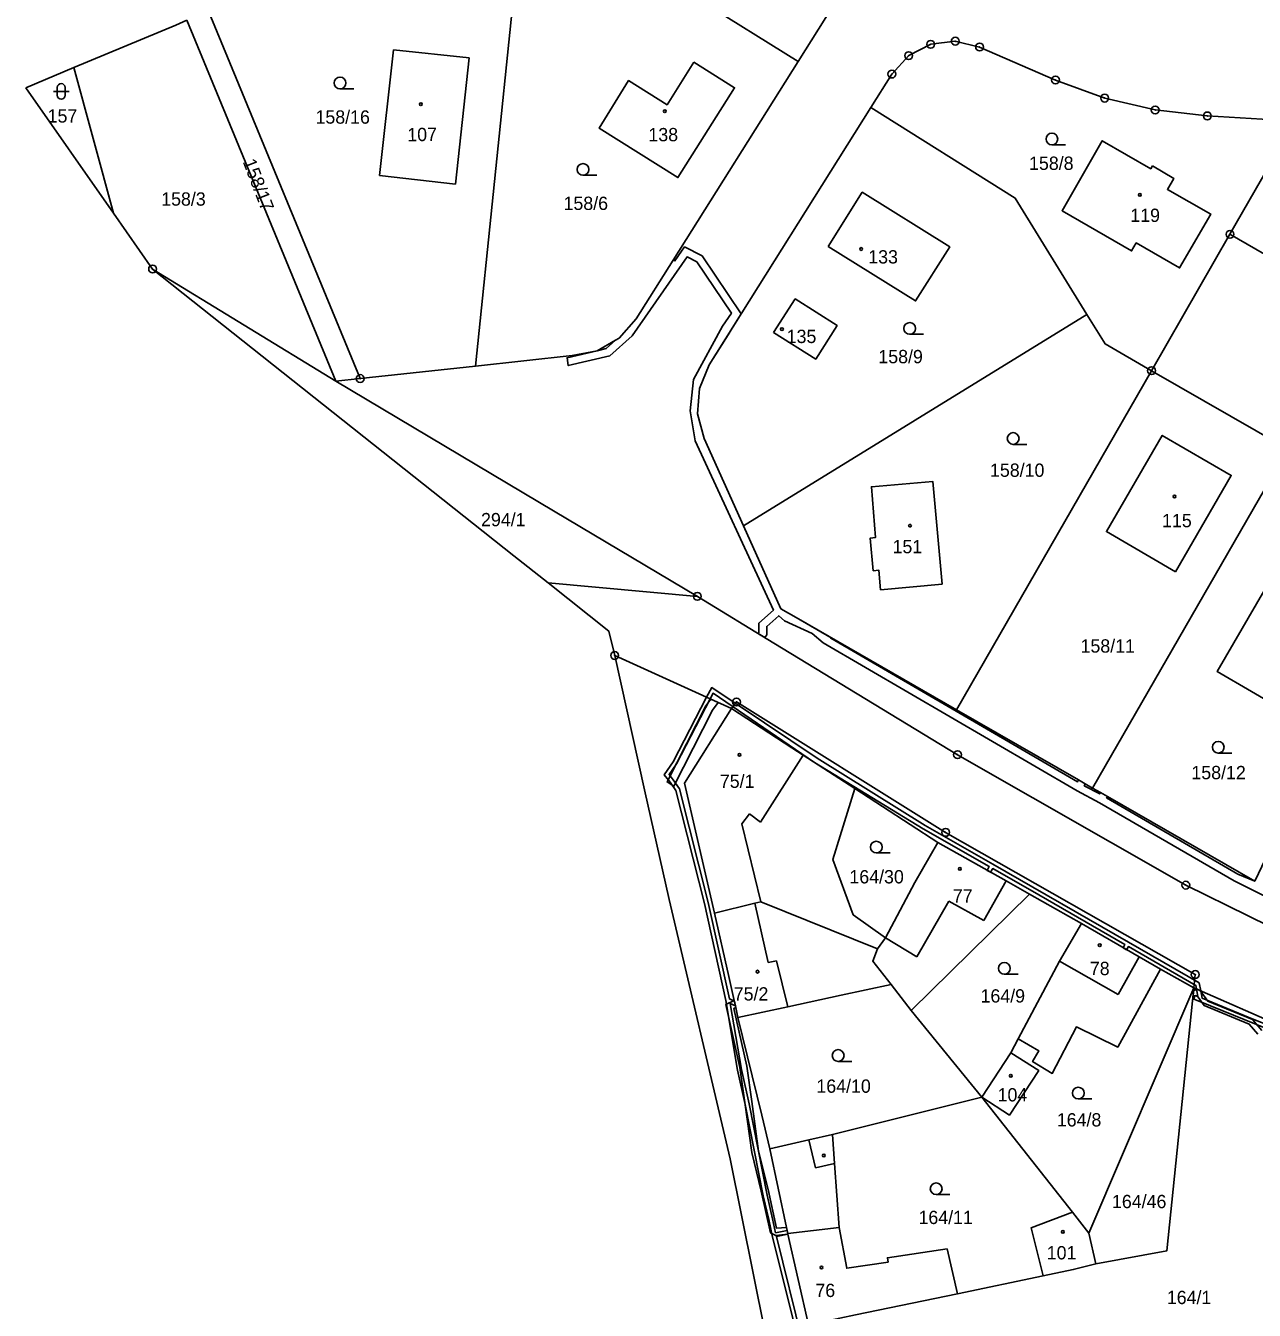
# Model space of a CAD drawing. Extents: x -779723 to -777378, y -1011169 to -1009297.
# Drawn here: x -779529.1 to -779372, y -1010177.1 to -1010012.9 of the extents above; entities that cross this region are included whole.
import ezdxf

# ---------------------------------------------------------------- set-up
doc = ezdxf.new("R2010")
doc.units = 0
for name, color, linetype in [('Hranice parcel', 7, 'Continuous'), ('Parcelní čísla', 7, 'Continuous'), ('Vnitřní kresba', 7, 'Continuous'), ('Věcná břemena k části', 7, 'Continuous'), ('Značky bodu BP', 7, 'Continuous'), ('Značky budov', 7, 'Continuous'), ('Značky kultur', 7, 'Continuous')]:
    doc.layers.add(name, color=color, linetype=linetype)

msp = doc.modelspace()

# ---------------------------------------------------------------- linework, layer by layer
at = {"layer": 'Hranice parcel'}
for p, q in [((-779405.63, -1009978.11), (-779430.36, -1010017.45)), ((-779466.49, -1010007.04), (-779471.6, -1010056.37)), ((-779505.72, -1010011.01), (-779486.32, -1010057.97)), ((-779489.42, -1010058.31), (-779508.48, -1010012.18)), ((-779522.9, -1010018.23), (-779529.07, -1010020.81)), ((-779517.85, -1010036.84), (-779522.9, -1010018.23)), ((-779529.07, -1010020.81), (-779517.85, -1010036.84)), ((-779517.85, -1010036.84), (-779512.85, -1010043.97)), ((-779385.17, -1010056.96), (-779375.15, -1010039.53)), ((-779512.85, -1010043.97), (-779489.42, -1010058.31)), ((-779512.85, -1010043.97), (-779466.67, -1010080.62)), ((-779437.34, -1010076.8), (-779393.43, -1010049.78)), ((-779459.24, -1010055.03), (-779471.6, -1010056.37)), ((-779471.6, -1010056.37), (-779486.32, -1010057.97)), ((-779410.1, -1010100.31), (-779385.17, -1010056.96)), ((-779367.78, -1010066.96), (-779385.17, -1010056.96)), ((-779486.32, -1010057.97), (-779489.42, -1010058.31)), ((-779392.71, -1010110.31), (-779367.78, -1010066.96)), ((-779466.67, -1010080.62), (-779462.29, -1010084.1)), ((-779462.29, -1010084.1), (-779443.22, -1010085.81)), ((-779412.49, -1010117.26), (-779423.11, -1010110.38)), ((-779415.89, -1010138.74), (-779400.78, -1010123.88)), ((-779394.14, -1010127.63), (-779400.78, -1010123.88)), ((-779420.18, -1010130.88), (-779419.17, -1010129.45)), ((-779379.75, -1010135.84), (-779384.01, -1010133.48)), ((-779418.47, -1010135.43), (-779415.89, -1010138.74)), ((-779393.19, -1010167.19), (-779379.75, -1010135.84)), ((-779368.25, -1010140.93), (-779379.75, -1010135.84)), ((-779415.89, -1010138.74), (-779406.87, -1010149.81)), ((-779402.22, -1010142.37), (-779403.16, -1010144.15)), ((-779406.87, -1010149.81), (-779403.16, -1010144.15)), ((-779425.97, -1010154.58), (-779406.87, -1010149.81)), ((-779406.87, -1010149.81), (-779395.28, -1010164.54)), ((-779395.28, -1010164.54), (-779393.19, -1010167.19)), ((-779392.31, -1010171.12), (-779393.19, -1010167.19)), ((-779409.96, -1010174.94), (-779411.28, -1010169.22)), ((-779399.03, -1010172.67), (-779409.96, -1010174.94))]:
    msp.add_line(p, q, dxfattribs=at)
for points in [[(-779430.36, -1010017.45), (-779443.07, -1010009.46), (-779466.49, -1010007.04)], [(-779508.48, -1010012.18), (-779509.9, -1010012.78), (-779522.9, -1010018.23)], [(-779482.07, -1010015.94), (-779472.39, -1010016.99), (-779474.14, -1010033.11), (-779483.83, -1010032.01), (-779482.07, -1010015.94)], [(-779421.04, -1010023.31), (-779418.36, -1010019.05), (-779416.21, -1010016.69), (-779413.4, -1010015.24), (-779410.26, -1010014.85), (-779407.15, -1010015.59), (-779397.45, -1010019.81), (-779391.16, -1010022.12), (-779384.71, -1010023.64), (-779378.05, -1010024.4), (-779366.83, -1010025.07)], [(-779430.36, -1010017.45), (-779446.32, -1010042.84), (-779451.04, -1010050.34), (-779453.2, -1010052.79), (-779453.68, -1010053.07), (-779456.04, -1010054.41), (-779459.24, -1010055.03)], [(-779443.68, -1010017.51), (-779438.46, -1010020.79), (-779445.71, -1010032.28), (-779455.79, -1010025.95), (-779452.01, -1010019.89), (-779447.1, -1010022.98), (-779443.68, -1010017.51)], [(-779437.34, -1010076.8), (-779442.37, -1010065.63), (-779443.2, -1010062.48), (-779442.97, -1010059.22), (-779441.71, -1010056.21), (-779421.04, -1010023.31)], [(-779421.04, -1010023.31), (-779402.59, -1010034.91), (-779393.43, -1010049.78)], [(-779375.15, -1010039.53), (-779371.1, -1010032.49), (-779369.72, -1010030.1), (-779366.83, -1010025.07)], [(-779385.04, -1010030.79), (-779382.33, -1010032.39), (-779383.14, -1010033.8), (-779377.61, -1010036.95), (-779381.6, -1010043.83), (-779387.12, -1010040.63), (-779387.72, -1010041.66), (-779396.61, -1010036.51), (-779391.47, -1010027.58), (-779385.28, -1010031.16), (-779385.04, -1010030.79)], [(-779426.49, -1010041.07), (-779422.15, -1010034.15), (-779410.97, -1010041.14), (-779415.34, -1010048.05), (-779426.49, -1010041.07)], [(-779341.93, -1010058.63), (-779356.91, -1010050.02), (-779361.56, -1010047.34), (-779375.15, -1010039.53)], [(-779433.48, -1010052.09), (-779430.71, -1010047.79), (-779425.37, -1010051.19), (-779428.1, -1010055.49), (-779433.48, -1010052.09)], [(-779393.43, -1010049.78), (-779391.11, -1010053.54), (-779385.17, -1010056.96)], [(-779489.42, -1010058.31), (-779461.6, -1010074.87), (-779443.22, -1010085.81)], [(-779382.13, -1010082.68), (-779390.94, -1010077.53), (-779383.8, -1010065.23), (-779374.99, -1010070.35), (-779382.13, -1010082.68)], [(-779411.92, -1010084.25), (-779419.8, -1010084.97), (-779420.01, -1010082.47), (-779420.75, -1010082.53), (-779421.12, -1010078.36), (-779420.44, -1010078.28), (-779420.98, -1010071.8), (-779413.13, -1010071.11), (-779411.92, -1010084.25)], [(-779410.1, -1010100.31), (-779430.6, -1010088.52), (-779432.57, -1010087.39), (-779437.34, -1010076.8)], [(-779350.39, -1010076.96), (-779371.98, -1010122.22), (-779390.82, -1010111.39), (-779391.69, -1010110.89), (-779392.71, -1010110.31)], [(-779368.02, -1010100.51), (-779376.78, -1010095.43), (-779369.65, -1010083.1), (-779360.78, -1010088.23), (-779368.02, -1010100.51)], [(-779462.29, -1010084.1), (-779454.55, -1010090.24), (-779453.79, -1010093.36)], [(-779443.22, -1010085.81), (-779433.43, -1010091.77), (-779409.97, -1010106.05), (-779380.8, -1010122.72), (-779356.88, -1010134.5), (-779331.75, -1010145.42), (-779302.03, -1010157.12), (-779292.12, -1010161.67)], [(-779438.86, -1010100.16), (-779441.59, -1010098.92), (-779442.04, -1010098.71), (-779453.79, -1010093.36)], [(-779453.79, -1010093.36), (-779449.96, -1010110.52), (-779446.83, -1010124.56)], [(-779438.86, -1010100.16), (-779444.86, -1010109.68), (-779441.05, -1010126.3)], [(-779423.11, -1010110.38), (-779429.69, -1010106.11), (-779431.13, -1010105.19), (-779438.86, -1010100.16)], [(-779392.71, -1010110.31), (-779393.65, -1010109.77), (-779394.52, -1010109.27), (-779410.1, -1010100.31)], [(-779419.17, -1010129.45), (-779423.3, -1010126.5), (-779425.9, -1010119.46), (-779423.11, -1010110.38)], [(-779412.49, -1010117.26), (-779415.42, -1010122.39), (-779419.17, -1010129.45)], [(-779400.78, -1010123.88), (-779403.77, -1010122.18), (-779412.49, -1010117.26)], [(-779446.83, -1010124.56), (-779439.02, -1010157.72), (-779433.12, -1010187.16), (-779423.51, -1010232.67)], [(-779441.05, -1010126.3), (-779435.89, -1010125.03), (-779435.11, -1010124.84), (-779420.18, -1010130.88)], [(-779441.05, -1010126.3), (-779439.21, -1010134.38), (-779438.5, -1010137.45), (-779438.29, -1010138.35), (-779438.03, -1010139.63)], [(-779394.14, -1010127.63), (-779396.93, -1010132.43), (-779402.22, -1010142.37)], [(-779384.01, -1010133.48), (-779386.76, -1010131.89), (-779394.14, -1010127.63)], [(-779418.47, -1010135.43), (-779420.81, -1010132.43), (-779420.18, -1010130.88)], [(-779402.22, -1010142.37), (-779399.58, -1010143.89), (-779400.38, -1010145.27), (-779397.87, -1010146.79), (-779394.77, -1010140.85), (-779389.49, -1010143.43), (-779384.01, -1010133.48)], [(-779438.03, -1010139.63), (-779431.67, -1010138.26), (-779424.85, -1010136.8), (-779418.47, -1010135.43)], [(-779379.75, -1010135.84), (-779383.22, -1010169.47), (-779392.31, -1010171.12)], [(-779433.96, -1010156.43), (-779435, -1010152.13), (-779438.03, -1010139.63)], [(-779403.16, -1010144.15), (-779399.6, -1010146.43), (-779403.35, -1010152.12), (-779406.87, -1010149.81)], [(-779425.97, -1010154.58), (-779428.99, -1010155.28), (-779433.96, -1010156.43)], [(-779418.85, -1010170.93), (-779424.13, -1010171.7), (-779425.12, -1010166.48), (-779425.7, -1010158.32), (-779425.97, -1010154.58)], [(-779433.96, -1010156.43), (-779431.85, -1010166.47), (-779431.68, -1010167.23), (-779431.65, -1010167.35), (-779429.01, -1010178.94), (-779423, -1010177.65), (-779409.96, -1010174.94)], [(-779399.03, -1010172.67), (-779400.55, -1010166.52), (-779395.28, -1010164.54)], [(-779411.28, -1010169.22), (-779418.94, -1010170.34), (-779418.85, -1010170.93)], [(-779392.31, -1010171.12), (-779395.19, -1010171.87), (-779399.03, -1010172.67)]]:
    msp.add_lwpolyline(points, dxfattribs=at)
at = {"layer": 'Vnitřní kresba'}
for p, q in [((-779438.22, -1010099.31), (-779438.86, -1010100.16)), ((-779411.49, -1010115.98), (-779438.22, -1010099.31)), ((-779429.69, -1010106.11), (-779435.16, -1010114.65)), ((-779436.55, -1010113.62), (-779437.52, -1010114.87)), ((-779435.16, -1010114.65), (-779436.55, -1010113.62)), ((-779437.52, -1010114.87), (-779435.11, -1010124.84)), ((-779379.59, -1010134.15), (-779411.49, -1010115.98)), ((-779403.77, -1010122.18), (-779406.62, -1010127.23)), ((-779434.17, -1010132.62), (-779435.89, -1010125.03)), ((-779415.18, -1010131.88), (-779411.09, -1010124.77)), ((-779411.09, -1010124.77), (-779406.62, -1010127.23)), ((-779419.17, -1010129.45), (-779415.18, -1010131.88)), ((-779433.09, -1010132.38), (-779434.17, -1010132.62)), ((-779431.67, -1010138.26), (-779433.09, -1010132.38)), ((-779396.93, -1010132.43), (-779389.44, -1010136.7)), ((-779389.44, -1010136.7), (-779386.76, -1010131.89)), ((-779379.75, -1010135.84), (-779379.59, -1010134.15)), ((-779428.99, -1010155.28), (-779428.14, -1010158.86)), ((-779428.14, -1010158.86), (-779425.7, -1010158.32)), ((-779431.68, -1010167.23), (-779425.12, -1010166.48))]:
    msp.add_line(p, q, dxfattribs=at)
at = {"layer": 'Věcná břemena k části'}
for points in [[(-779371.98, -1010122.22), (-779374.14, -1010121.3), (-779390.92, -1010111.56), (-779390.82, -1010111.39), (-779391.69, -1010110.89), (-779391.79, -1010111.07), (-779393.77, -1010110.02), (-779393.65, -1010109.77), (-779394.52, -1010109.27), (-779394.64, -1010109.53), (-779426.17, -1010091.16), (-779426.13, -1010091.09), (-779430.6, -1010088.52), (-779432.57, -1010087.39), (-779437.34, -1010076.8), (-779442.37, -1010065.63), (-779443.2, -1010062.48), (-779442.97, -1010059.22), (-779441.71, -1010056.21), (-779439.29, -1010052.36), (-779438.76, -1010051.51), (-779437.61, -1010049.69), (-779442.63, -1010042.28), (-779444.85, -1010041.15), (-779446.09, -1010042.94), (-779446.32, -1010042.84), (-779451.04, -1010050.34), (-779453.2, -1010052.79), (-779453.68, -1010053.07), (-779454.87, -1010054.13), (-779456.04, -1010054.41), (-779459.87, -1010055.3), (-779459.73, -1010056.3), (-779454.39, -1010055.05), (-779451.55, -1010052.49), (-779444.53, -1010042.43), (-779443.31, -1010043.06), (-779438.87, -1010049.63), (-779440.01, -1010051.28), (-779443.73, -1010058.09), (-779444.14, -1010062.11), (-779443.51, -1010065.94), (-779433.51, -1010087.57), (-779435.35, -1010089.22), (-779435.35, -1010090.42), (-779435.44, -1010090.55), (-779434.59, -1010091.07), (-779434.35, -1010090.74), (-779434.35, -1010089.66), (-779432.82, -1010088.28), (-779432.07, -1010088.95), (-779428.57, -1010090.55), (-779427.14, -1010091.75), (-779394.67, -1010110.67), (-779391.84, -1010112.18), (-779374.62, -1010122.18), (-779362.56, -1010128.21)], [(-779429.82, -1010180.92), (-779433.11, -1010167.64), (-779431.65, -1010167.35), (-779431.76, -1010166.87), (-779433.23, -1010167.15), (-779433.61, -1010165.38), (-779434.32, -1010162.35), (-779436.62, -1010150.67), (-779437.6, -1010146.28), (-779439.02, -1010137.86), (-779438.34, -1010138.15), (-779438.47, -1010137.56), (-779439.13, -1010137.26), (-779441.83, -1010124.95), (-779445.5, -1010110.39), (-779446.3, -1010109.27), (-779446.83, -1010108.58), (-779445.91, -1010107.22), (-779441.59, -1010098.92), (-779442.04, -1010098.71), (-779446.33, -1010106.96), (-779447.45, -1010108.6), (-779446.7, -1010109.56), (-779445.96, -1010110.61), (-779442.31, -1010125.06), (-779439.59, -1010137.47), (-779438.1, -1010146.38), (-779437.1, -1010150.77), (-779434.8, -1010162.45), (-779434.09, -1010165.48), (-779433.66, -1010167.49), (-779430.3, -1010181.02)], [(-779371.08, -1010141.28), (-779372.26, -1010139.91), (-779378, -1010137.54), (-779378.94, -1010136.2), (-779379.75, -1010135.84), (-779379.6, -1010136.04), (-779379.57, -1010136.14), (-779379.78, -1010136.13), (-779379.85, -1010136.83), (-779379.36, -1010136.85), (-779378.46, -1010138.12), (-779372.68, -1010140.49), (-779371.58, -1010141.77)], [(-779369.93, -1010140.74), (-779372.11, -1010139.91), (-779378.69, -1010137.17), (-779378.87, -1010136.23), (-779379.43, -1010135.98), (-779379.24, -1010136.97), (-779379.62, -1010136.83), (-779379.78, -1010137.3), (-779379, -1010137.58), (-779370.39, -1010141.1)]]:
    msp.add_lwpolyline(points, dxfattribs=at)
for points in [[(-779378.87, -1010136.23), (-779379.07, -1010135.22), (-779388.11, -1010130.01), (-779405.45, -1010120.04), (-779414.11, -1010115.1), (-779427.92, -1010106.51), (-779441.39, -1010097.47), (-779442.04, -1010098.71), (-779441.59, -1010098.92), (-779441.21, -1010098.19), (-779428.26, -1010107.04), (-779414.36, -1010115.52), (-779405.91, -1010120.35), (-779406.17, -1010120.83), (-779405.74, -1010121.07), (-779405.47, -1010120.6), (-779399.57, -1010123.97), (-779388.57, -1010130.32), (-779388.79, -1010130.72), (-779388.36, -1010130.97), (-779388.14, -1010130.57), (-779379.51, -1010135.54), (-779379.43, -1010135.98)], [(-779441.27, -1010100.34), (-779440.58, -1010099.38), (-779441.51, -1010098.95), (-779442.13, -1010099.82), (-779447.09, -1010109.53), (-779446.25, -1010110.07)], [(-779437.8, -1010146.01), (-779437.16, -1010150.5), (-779436.27, -1010156.9), (-779435.05, -1010161.83), (-779433.87, -1010167.17), (-779433.21, -1010167.52), (-779431.65, -1010167.35), (-779431.68, -1010167.23), (-779431.85, -1010166.47), (-779433.09, -1010166.57), (-779434.17, -1010161.63), (-779435.39, -1010156.72), (-779436.26, -1010150.38), (-779436.92, -1010145.85), (-779438.56, -1010138.48), (-779438.29, -1010138.35), (-779438.5, -1010137.45), (-779439.6, -1010137.98)]]:
    msp.add_lwpolyline(points, close=True, dxfattribs=at)
at = {"layer": 'Značky bodu BP'}
for centre, radius in [((-779410.26, -1010014.85), 0.5), ((-779413.4, -1010015.24), 0.5), ((-779413.4, -1010015.24), 0.0303), ((-779410.26, -1010014.85), 0.0303), ((-779407.15, -1010015.59), 0.5), ((-779407.15, -1010015.59), 0.0303), ((-779416.21, -1010016.69), 0.5), ((-779416.21, -1010016.69), 0.0303), ((-779418.36, -1010019.05), 0.5), ((-779418.36, -1010019.05), 0.0303), ((-779397.45, -1010019.81), 0.5), ((-779397.45, -1010019.81), 0.0303), ((-779391.16, -1010022.12), 0.5), ((-779391.16, -1010022.12), 0.0303), ((-779384.71, -1010023.64), 0.5), ((-779384.71, -1010023.64), 0.0303), ((-779378.05, -1010024.4), 0.5), ((-779378.05, -1010024.4), 0.0303), ((-779375.15, -1010039.53), 0.5), ((-779375.15, -1010039.53), 0.0303), ((-779512.85, -1010043.97), 0.5), ((-779512.85, -1010043.97), 0.0303), ((-779385.17, -1010056.96), 0.5), ((-779385.17, -1010056.96), 0.0303), ((-779486.32, -1010057.97), 0.5), ((-779486.32, -1010057.97), 0.0303), ((-779443.22, -1010085.81), 0.5), ((-779443.22, -1010085.81), 0.0303), ((-779453.79, -1010093.36), 0.5), ((-779453.79, -1010093.36), 0.0303), ((-779438.22, -1010099.31), 0.5), ((-779438.22, -1010099.31), 0.0303), ((-779409.97, -1010106.05), 0.5), ((-779409.97, -1010106.05), 0.0303), ((-779411.49, -1010115.98), 0.5), ((-779411.49, -1010115.98), 0.0303), ((-779380.8, -1010122.72), 0.5), ((-779380.8, -1010122.72), 0.0303), ((-779379.59, -1010134.15), 0.5), ((-779379.59, -1010134.15), 0.0303)]:
    msp.add_circle(centre, radius, dxfattribs=at)
at = {"layer": 'Značky budov'}
for centre in [(-779478.56, -1010022.91), (-779447.38, -1010023.8), (-779386.66, -1010034.5), (-779422.28, -1010041.41), (-779432.41, -1010051.64), (-779382.23, -1010073.06), (-779416.05, -1010076.77), (-779437.85, -1010106.08), (-779409.67, -1010120.65), (-779391.8, -1010130.39), (-779435.52, -1010133.78), (-779403.17, -1010147.09), (-779427.07, -1010157.27), (-779396.5, -1010167.04), (-779427.36, -1010171.61)]:
    msp.add_circle(centre, 0.175, dxfattribs=at)
at = {"layer": 'Značky kultur'}
for p, q in [((-779525.03, -1010020.76), (-779525.03, -1010021.76)), ((-779524.03, -1010021.76), (-779524.03, -1010020.76)), ((-779488.89, -1010020.94), (-779487.14, -1010020.94)), ((-779525.53, -1010021.26), (-779523.53, -1010021.26)), ((-779397.91, -1010028.1), (-779396.16, -1010028.1)), ((-779457.84, -1010031.99), (-779456.09, -1010031.99)), ((-779416.08, -1010052.31), (-779414.33, -1010052.31)), ((-779402.86, -1010066.38), (-779401.11, -1010066.38)), ((-779376.65, -1010105.84), (-779374.9, -1010105.84)), ((-779420.35, -1010118.61), (-779418.6, -1010118.61)), ((-779403.99, -1010134.11), (-779402.24, -1010134.11)), ((-779425.23, -1010145.25), (-779423.48, -1010145.25)), ((-779394.54, -1010150.05), (-779392.79, -1010150.05)), ((-779412.7, -1010162.28), (-779410.95, -1010162.28))]:
    msp.add_line(p, q, dxfattribs=at)
for centre in [(-779488.89, -1010020.19), (-779397.91, -1010027.35), (-779457.84, -1010031.24), (-779416.08, -1010051.56), (-779402.86, -1010065.63), (-779376.65, -1010105.09), (-779420.35, -1010117.86), (-779403.99, -1010133.36), (-779425.23, -1010144.5), (-779394.54, -1010149.3), (-779412.7, -1010161.53)]:
    msp.add_circle(centre, 0.75, dxfattribs=at)
for centre, start, end in [((-779524.53, -1010020.76), 0, 180), ((-779524.53, -1010021.76), 180, 359.9879)]:
    msp.add_arc(centre, 0.5, start, end, dxfattribs=at)

# ---------------------------------------------------------------- texts
at = {"layer": 'Parcelní čísla'}
for s, p in [('157', (-779526.27, -1010025.25)), ('158/16', (-779492.03, -1010025.39)), ('138', (-779449.48, -1010027.64)), ('158/8', (-779400.83, -1010031.3)), ('158/3', (-779511.75, -1010035.87)), ('158/6', (-779460.33, -1010036.42)), ('119', (-779387.89, -1010037.95)), ('133', (-779421.38, -1010043.26)), ('135', (-779431.81, -1010053.43)), ('158/9', (-779420.09, -1010056.01)), ('158/10', (-779405.82, -1010070.53)), ('294/1', (-779470.87, -1010076.85)), ('115', (-779383.83, -1010076.97)), ('151', (-779418.28, -1010080.3)), ('158/11', (-779394.25, -1010093)), ('158/12', (-779380.08, -1010109.18)), ('75/1', (-779440.35, -1010110.29)), ('164/30', (-779423.79, -1010122.5)), ('77', (-779410.57, -1010124.94)), ('78', (-779393.06, -1010134.22)), ('75/2', (-779438.57, -1010137.47)), ('164/9', (-779407.03, -1010137.73)), ('164/10', (-779428.01, -1010149.26)), ('104', (-779404.85, -1010150.37)), ('164/8', (-779397.28, -1010153.57)), ('164/46', (-779390.23, -1010164.01)), ('164/11', (-779414.96, -1010166.04)), ('101', (-779398.57, -1010170.56)), ('76', (-779428.14, -1010175.37)), ('164/1', (-779383.22, -1010176.27))]:
    msp.add_text(s, height=1.7, dxfattribs=at).set_placement(p)
for s, rotation, p in [('107', 1, (-779480.28, -1010027.65)), ('158/17', 291, (-779501.35, -1010030.25))]:
    msp.add_text(s, height=1.7, rotation=rotation, dxfattribs=at).set_placement(p)

doc.saveas('drawing.dxf')
